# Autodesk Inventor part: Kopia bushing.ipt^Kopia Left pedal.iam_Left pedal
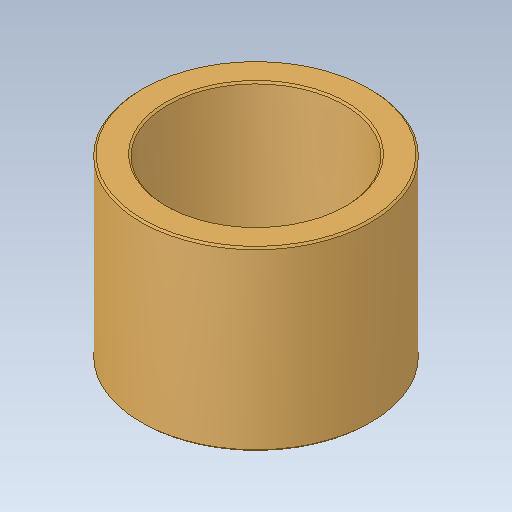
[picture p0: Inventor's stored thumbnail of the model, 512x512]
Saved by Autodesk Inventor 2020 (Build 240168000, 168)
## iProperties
Created: 2017-10
Part Number: Kopia bushing.ipt^Kopia Left pedal.iam_Left pedal
Material: solidworks materials|Mosiądz|27
Document SubType Name: Modeling
Designer: Tomasz
Density: 8.5 g/cm^3
Appearance: 211,170,33
Sending System: SolidWorks 2017
Last Author: Tomasz
Last Saved: 2017-11-19
Author: Tomasz
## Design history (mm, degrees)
feature "bushing.ipt"
node "Bryła1"
